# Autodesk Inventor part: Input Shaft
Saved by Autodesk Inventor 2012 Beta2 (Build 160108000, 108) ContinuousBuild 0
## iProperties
Created: 2011-01
Part Number: Input Shaft
Material: Steel
Document SubType Name: Modeling
Designer: Beta-8540w
Density: 1 g/cm^3
CustomPartVersion: 1
Author: Beta-8540w
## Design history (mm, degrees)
sketch "Main Sketch"
  geometry: L1 (0, 0)-(43, 0) reference; L2 (0, 0)-(0, 45); L3 (12, 45)-(12, 6); L4 (0, 45)-(12, 45); L5 (15, 6)-(15, 5); L6 (12, 6)-(15, 6); L7 (43, 5)-(43, 0); L8 (15, 5)-(43, 5)
  constraints: 16 end point, 5 horizontal, 4 vertical
  dimensions: "d3" = 90 diameter of L4 L1 (derived); "d4" = 12 diameter of L6 L1 (derived); "d5" = 10 diameter of L8 L1 (derived)
revolve "Revolution1" sketch "Main Sketch" stored, may be unused: angle "d6" = 0 deg
chamfer "Chamfer1" distance "d7" = 0.5; stored, may be unused: second distance "d8" = 0.125, angle "d9" = 45 deg
node "Retaining Ring Groove1"
node "Spur Gear Teeth1"
body "Solid1"
feature "iFeature27:1"
feature "Spur Gear Feature 2"
other parameters: "d0" = 0, "d1" = 0, "d2" = 0
